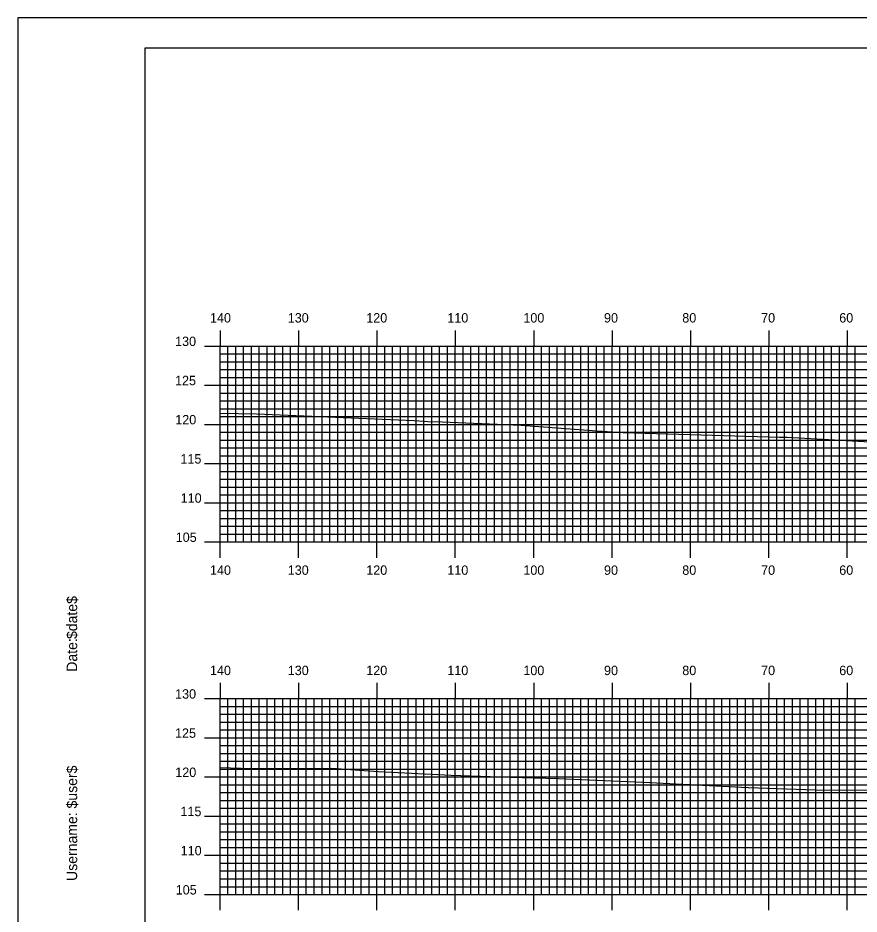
# Model space of a CAD drawing. Extents: x 1780680 to 1781023, y 442591 to 442811.
# Drawn here: x 1780679.6 to 1780786.9, y 442696.2 to 442810.5 of the extents above; entities that cross this region are included whole.
import ezdxf

# ---------------------------------------------------------------- set-up
doc = ezdxf.new("R2010")
doc.units = 0
for name, color, linetype in [('BORDER', 7, 'Continuous'), ('H_V ANNOTATION', 7, 'Continuous'), ('MAJOR', 7, 'Continuous'), ('MINOR', 7, 'Continuous'), ('PLOT BOUNDARY', 7, 'Continuous'), ('S_Roadway_Centerline', 7, 'Continuous')]:
    doc.layers.add(name, color=color, linetype=linetype)

msp = doc.modelspace()

# ---------------------------------------------------------------- linework, layer by layer
at = {"layer": 'BORDER'}
msp.add_lwpolyline([(1780695.78, 442596.67), (1781015.78, 442596.67), (1781015.78, 442806.67), (1780695.78, 442806.67)], close=True, dxfattribs=at)
at = {"layer": 'MAJOR'}
for p, q in [((1780705.38, 442770.67), (1780705.38, 442768.67)), ((1780715.38, 442770.67), (1780715.38, 442768.67)), ((1780725.38, 442770.67), (1780725.38, 442768.67)), ((1780735.38, 442770.67), (1780735.38, 442768.67)), ((1780745.38, 442770.67), (1780745.38, 442768.67)), ((1780755.38, 442770.67), (1780755.38, 442768.67)), ((1780765.38, 442770.67), (1780765.38, 442768.67)), ((1780775.38, 442770.67), (1780775.38, 442768.67)), ((1780785.38, 442770.67), (1780785.38, 442768.67)), ((1780703.38, 442768.67), (1780705.38, 442768.67)), ((1780705.38, 442768.67), (1780985.38, 442768.67)), ((1780705.38, 442743.67), (1780705.38, 442768.67)), ((1780705.38, 442743.67), (1780705.38, 442768.67)), ((1780705.38, 442768.67), (1780985.38, 442768.67)), ((1780715.38, 442743.67), (1780715.38, 442768.67)), ((1780725.38, 442743.67), (1780725.38, 442768.67)), ((1780735.38, 442743.67), (1780735.38, 442768.67)), ((1780745.38, 442743.67), (1780745.38, 442768.67)), ((1780755.38, 442743.67), (1780755.38, 442768.67)), ((1780765.38, 442743.67), (1780765.38, 442768.67)), ((1780775.38, 442743.67), (1780775.38, 442768.67)), ((1780785.38, 442743.67), (1780785.38, 442768.67)), ((1780703.38, 442763.67), (1780705.38, 442763.67)), ((1780705.38, 442763.67), (1780985.38, 442763.67)), ((1780703.38, 442758.67), (1780705.38, 442758.67)), ((1780705.38, 442758.67), (1780985.38, 442758.67)), ((1780703.38, 442753.67), (1780705.38, 442753.67)), ((1780705.38, 442753.67), (1780985.38, 442753.67)), ((1780703.38, 442748.67), (1780705.38, 442748.67)), ((1780705.38, 442748.67), (1780985.38, 442748.67)), ((1780703.38, 442743.67), (1780705.38, 442743.67)), ((1780705.38, 442743.67), (1780985.38, 442743.67)), ((1780705.38, 442743.67), (1780985.38, 442743.67)), ((1780705.38, 442741.66), (1780705.38, 442743.67)), ((1780715.38, 442741.66), (1780715.38, 442743.67)), ((1780725.38, 442741.66), (1780725.38, 442743.67)), ((1780735.38, 442741.66), (1780735.38, 442743.67)), ((1780745.38, 442741.66), (1780745.38, 442743.67)), ((1780755.38, 442741.66), (1780755.38, 442743.67)), ((1780765.38, 442741.66), (1780765.38, 442743.67)), ((1780775.38, 442741.66), (1780775.38, 442743.67)), ((1780785.38, 442741.66), (1780785.38, 442743.67)), ((1780705.38, 442725.67), (1780705.38, 442723.67)), ((1780715.38, 442725.67), (1780715.38, 442723.67)), ((1780725.38, 442725.67), (1780725.38, 442723.67)), ((1780735.38, 442725.67), (1780735.38, 442723.67)), ((1780745.38, 442725.67), (1780745.38, 442723.67)), ((1780755.38, 442725.67), (1780755.38, 442723.67)), ((1780765.38, 442725.67), (1780765.38, 442723.67)), ((1780775.38, 442725.67), (1780775.38, 442723.67)), ((1780785.38, 442725.67), (1780785.38, 442723.67)), ((1780703.38, 442723.67), (1780705.38, 442723.67)), ((1780705.38, 442723.67), (1780985.38, 442723.67)), ((1780705.38, 442698.67), (1780705.38, 442723.67)), ((1780705.38, 442698.67), (1780705.38, 442723.67)), ((1780705.38, 442723.67), (1780985.38, 442723.67)), ((1780715.38, 442698.67), (1780715.38, 442723.67)), ((1780725.38, 442698.67), (1780725.38, 442723.67)), ((1780735.38, 442698.67), (1780735.38, 442723.67)), ((1780745.38, 442698.67), (1780745.38, 442723.67)), ((1780755.38, 442698.67), (1780755.38, 442723.67)), ((1780765.38, 442698.67), (1780765.38, 442723.67)), ((1780775.38, 442698.67), (1780775.38, 442723.67)), ((1780785.38, 442698.67), (1780785.38, 442723.67)), ((1780703.38, 442718.67), (1780705.38, 442718.67)), ((1780705.38, 442718.67), (1780985.38, 442718.67)), ((1780703.38, 442713.67), (1780705.38, 442713.67)), ((1780705.38, 442713.67), (1780985.38, 442713.67)), ((1780703.38, 442708.67), (1780705.38, 442708.67)), ((1780705.38, 442708.67), (1780985.38, 442708.67)), ((1780703.38, 442703.67), (1780705.38, 442703.67)), ((1780705.38, 442703.67), (1780985.38, 442703.67)), ((1780703.38, 442698.67), (1780705.38, 442698.67)), ((1780705.38, 442698.67), (1780985.38, 442698.67)), ((1780705.38, 442698.67), (1780985.38, 442698.67)), ((1780705.38, 442696.66), (1780705.38, 442698.67)), ((1780715.38, 442696.66), (1780715.38, 442698.67)), ((1780725.38, 442696.66), (1780725.38, 442698.67)), ((1780735.38, 442696.66), (1780735.38, 442698.67)), ((1780745.38, 442696.66), (1780745.38, 442698.67)), ((1780755.38, 442696.66), (1780755.38, 442698.67)), ((1780765.38, 442696.66), (1780765.38, 442698.67)), ((1780775.38, 442696.66), (1780775.38, 442698.67)), ((1780785.38, 442696.66), (1780785.38, 442698.67))]:
    msp.add_line(p, q, dxfattribs=at)
at = {"layer": 'MINOR'}
for p, q in [((1780705.38, 442767.67), (1780985.38, 442767.67)), ((1780705.38, 442767.67), (1780707.39, 442767.67)), ((1780706.38, 442743.67), (1780706.38, 442768.67)), ((1780707.38, 442743.67), (1780707.38, 442768.67)), ((1780708.38, 442743.67), (1780708.38, 442768.67)), ((1780709.38, 442743.67), (1780709.38, 442768.67)), ((1780710.38, 442743.67), (1780710.38, 442768.67)), ((1780711.38, 442743.67), (1780711.38, 442768.67)), ((1780712.38, 442743.67), (1780712.38, 442768.67)), ((1780713.38, 442743.67), (1780713.38, 442768.67)), ((1780714.38, 442743.67), (1780714.38, 442768.67)), ((1780716.38, 442743.67), (1780716.38, 442768.67)), ((1780717.38, 442743.67), (1780717.38, 442768.67)), ((1780718.38, 442743.67), (1780718.38, 442768.67)), ((1780719.38, 442743.67), (1780719.38, 442768.67)), ((1780720.38, 442743.67), (1780720.38, 442768.67)), ((1780721.38, 442743.67), (1780721.38, 442768.67)), ((1780722.38, 442743.67), (1780722.38, 442768.67)), ((1780723.38, 442743.67), (1780723.38, 442768.67)), ((1780724.38, 442743.67), (1780724.38, 442768.67)), ((1780726.38, 442743.67), (1780726.38, 442768.67)), ((1780727.38, 442743.67), (1780727.38, 442768.67)), ((1780728.38, 442743.67), (1780728.38, 442768.67)), ((1780729.38, 442743.67), (1780729.38, 442768.67)), ((1780730.38, 442743.67), (1780730.38, 442768.67)), ((1780731.38, 442743.67), (1780731.38, 442768.67)), ((1780732.38, 442743.67), (1780732.38, 442768.67)), ((1780733.38, 442743.67), (1780733.38, 442768.67)), ((1780734.38, 442743.67), (1780734.38, 442768.67)), ((1780736.38, 442743.67), (1780736.38, 442768.67)), ((1780737.38, 442743.67), (1780737.38, 442768.67)), ((1780738.38, 442743.67), (1780738.38, 442768.67)), ((1780739.38, 442743.67), (1780739.38, 442768.67)), ((1780740.38, 442743.67), (1780740.38, 442768.67)), ((1780741.38, 442743.67), (1780741.38, 442768.67)), ((1780742.38, 442743.67), (1780742.38, 442768.67)), ((1780743.38, 442743.67), (1780743.38, 442768.67)), ((1780744.38, 442743.67), (1780744.38, 442768.67)), ((1780746.38, 442743.67), (1780746.38, 442768.67)), ((1780747.38, 442743.67), (1780747.38, 442768.67)), ((1780748.38, 442743.67), (1780748.38, 442768.67)), ((1780749.38, 442743.67), (1780749.38, 442768.67)), ((1780750.38, 442743.67), (1780750.38, 442768.67)), ((1780751.38, 442743.67), (1780751.38, 442768.67)), ((1780752.38, 442743.67), (1780752.38, 442768.67)), ((1780753.38, 442743.67), (1780753.38, 442768.67)), ((1780754.38, 442743.67), (1780754.38, 442768.67)), ((1780756.38, 442743.67), (1780756.38, 442768.67)), ((1780757.38, 442743.67), (1780757.38, 442768.67)), ((1780758.38, 442743.67), (1780758.38, 442768.67)), ((1780759.38, 442743.67), (1780759.38, 442768.67)), ((1780760.38, 442743.67), (1780760.38, 442768.67)), ((1780761.38, 442743.67), (1780761.38, 442768.67)), ((1780762.38, 442743.67), (1780762.38, 442768.67)), ((1780763.38, 442743.67), (1780763.38, 442768.67)), ((1780764.38, 442743.67), (1780764.38, 442768.67)), ((1780766.38, 442743.67), (1780766.38, 442768.67)), ((1780767.38, 442743.67), (1780767.38, 442768.67)), ((1780768.38, 442743.67), (1780768.38, 442768.67)), ((1780769.38, 442743.67), (1780769.38, 442768.67)), ((1780770.38, 442743.67), (1780770.38, 442768.67)), ((1780771.38, 442743.67), (1780771.38, 442768.67)), ((1780772.38, 442743.67), (1780772.38, 442768.67)), ((1780773.38, 442743.67), (1780773.38, 442768.67)), ((1780774.38, 442743.67), (1780774.38, 442768.67)), ((1780776.38, 442743.67), (1780776.38, 442768.67)), ((1780777.38, 442743.67), (1780777.38, 442768.67)), ((1780778.38, 442743.67), (1780778.38, 442768.67)), ((1780779.38, 442743.67), (1780779.38, 442768.67)), ((1780780.38, 442743.67), (1780780.38, 442768.67)), ((1780781.38, 442743.67), (1780781.38, 442768.67)), ((1780782.38, 442743.67), (1780782.38, 442768.67)), ((1780783.38, 442743.67), (1780783.38, 442768.67)), ((1780784.38, 442743.67), (1780784.38, 442768.67)), ((1780786.38, 442743.67), (1780786.38, 442768.67)), ((1780705.38, 442766.67), (1780985.38, 442766.67)), ((1780705.38, 442766.67), (1780707.39, 442766.67)), ((1780705.38, 442765.67), (1780985.38, 442765.67)), ((1780705.38, 442765.67), (1780707.39, 442765.67)), ((1780705.38, 442764.67), (1780985.38, 442764.67)), ((1780705.38, 442764.67), (1780707.39, 442764.67)), ((1780705.38, 442762.67), (1780985.38, 442762.67)), ((1780705.38, 442762.67), (1780707.39, 442762.67)), ((1780705.38, 442761.67), (1780985.38, 442761.67)), ((1780705.38, 442761.67), (1780707.39, 442761.67)), ((1780705.38, 442760.67), (1780985.38, 442760.67)), ((1780705.38, 442760.67), (1780707.39, 442760.67)), ((1780705.38, 442759.67), (1780985.38, 442759.67)), ((1780705.38, 442759.67), (1780707.39, 442759.67)), ((1780705.38, 442757.67), (1780985.38, 442757.67)), ((1780705.38, 442757.67), (1780707.39, 442757.67)), ((1780705.38, 442756.67), (1780985.38, 442756.67)), ((1780705.38, 442756.67), (1780707.39, 442756.67)), ((1780705.38, 442755.67), (1780985.38, 442755.67)), ((1780705.38, 442755.67), (1780707.39, 442755.67)), ((1780705.38, 442754.67), (1780985.38, 442754.67)), ((1780705.38, 442754.67), (1780707.39, 442754.67)), ((1780705.38, 442752.67), (1780985.38, 442752.67)), ((1780705.38, 442752.67), (1780707.39, 442752.67)), ((1780705.38, 442751.67), (1780985.38, 442751.67)), ((1780705.38, 442751.67), (1780707.39, 442751.67)), ((1780705.38, 442750.67), (1780985.38, 442750.67)), ((1780705.38, 442750.67), (1780707.39, 442750.67)), ((1780705.38, 442749.67), (1780985.38, 442749.67)), ((1780705.38, 442749.67), (1780707.39, 442749.67)), ((1780705.38, 442747.67), (1780985.38, 442747.67)), ((1780705.38, 442747.67), (1780707.39, 442747.67)), ((1780705.38, 442746.67), (1780985.38, 442746.67)), ((1780705.38, 442746.67), (1780707.39, 442746.67)), ((1780705.38, 442745.67), (1780985.38, 442745.67)), ((1780705.38, 442745.67), (1780707.39, 442745.67)), ((1780705.38, 442744.67), (1780985.38, 442744.67)), ((1780705.38, 442744.67), (1780707.39, 442744.67)), ((1780706.38, 442698.67), (1780706.38, 442723.67)), ((1780707.38, 442698.67), (1780707.38, 442723.67)), ((1780708.38, 442698.67), (1780708.38, 442723.67)), ((1780709.38, 442698.67), (1780709.38, 442723.67)), ((1780710.38, 442698.67), (1780710.38, 442723.67)), ((1780711.38, 442698.67), (1780711.38, 442723.67)), ((1780712.38, 442698.67), (1780712.38, 442723.67)), ((1780713.38, 442698.67), (1780713.38, 442723.67)), ((1780714.38, 442698.67), (1780714.38, 442723.67)), ((1780716.38, 442698.67), (1780716.38, 442723.67)), ((1780717.38, 442698.67), (1780717.38, 442723.67)), ((1780718.38, 442698.67), (1780718.38, 442723.67)), ((1780719.38, 442698.67), (1780719.38, 442723.67)), ((1780720.38, 442698.67), (1780720.38, 442723.67)), ((1780721.38, 442698.67), (1780721.38, 442723.67)), ((1780722.38, 442698.67), (1780722.38, 442723.67)), ((1780723.38, 442698.67), (1780723.38, 442723.67)), ((1780724.38, 442698.67), (1780724.38, 442723.67)), ((1780726.38, 442698.67), (1780726.38, 442723.67)), ((1780727.38, 442698.67), (1780727.38, 442723.67)), ((1780728.38, 442698.67), (1780728.38, 442723.67)), ((1780729.38, 442698.67), (1780729.38, 442723.67)), ((1780730.38, 442698.67), (1780730.38, 442723.67)), ((1780731.38, 442698.67), (1780731.38, 442723.67)), ((1780732.38, 442698.67), (1780732.38, 442723.67)), ((1780733.38, 442698.67), (1780733.38, 442723.67)), ((1780734.38, 442698.67), (1780734.38, 442723.67)), ((1780736.38, 442698.67), (1780736.38, 442723.67)), ((1780737.38, 442698.67), (1780737.38, 442723.67)), ((1780738.38, 442698.67), (1780738.38, 442723.67)), ((1780739.38, 442698.67), (1780739.38, 442723.67)), ((1780740.38, 442698.67), (1780740.38, 442723.67)), ((1780741.38, 442698.67), (1780741.38, 442723.67)), ((1780742.38, 442698.67), (1780742.38, 442723.67)), ((1780743.38, 442698.67), (1780743.38, 442723.67)), ((1780744.38, 442698.67), (1780744.38, 442723.67)), ((1780746.38, 442698.67), (1780746.38, 442723.67)), ((1780747.38, 442698.67), (1780747.38, 442723.67)), ((1780748.38, 442698.67), (1780748.38, 442723.67)), ((1780749.38, 442698.67), (1780749.38, 442723.67)), ((1780750.38, 442698.67), (1780750.38, 442723.67)), ((1780751.38, 442698.67), (1780751.38, 442723.67)), ((1780752.38, 442698.67), (1780752.38, 442723.67)), ((1780753.38, 442698.67), (1780753.38, 442723.67)), ((1780754.38, 442698.67), (1780754.38, 442723.67)), ((1780756.38, 442698.67), (1780756.38, 442723.67)), ((1780757.38, 442698.67), (1780757.38, 442723.67)), ((1780758.38, 442698.67), (1780758.38, 442723.67)), ((1780759.38, 442698.67), (1780759.38, 442723.67)), ((1780760.38, 442698.67), (1780760.38, 442723.67)), ((1780761.38, 442698.67), (1780761.38, 442723.67)), ((1780762.38, 442698.67), (1780762.38, 442723.67)), ((1780763.38, 442698.67), (1780763.38, 442723.67)), ((1780764.38, 442698.67), (1780764.38, 442723.67)), ((1780766.38, 442698.67), (1780766.38, 442723.67)), ((1780767.38, 442698.67), (1780767.38, 442723.67)), ((1780768.38, 442698.67), (1780768.38, 442723.67)), ((1780769.38, 442698.67), (1780769.38, 442723.67)), ((1780770.38, 442698.67), (1780770.38, 442723.67)), ((1780771.38, 442698.67), (1780771.38, 442723.67)), ((1780772.38, 442698.67), (1780772.38, 442723.67)), ((1780773.38, 442698.67), (1780773.38, 442723.67)), ((1780774.38, 442698.67), (1780774.38, 442723.67)), ((1780776.38, 442698.67), (1780776.38, 442723.67)), ((1780777.38, 442698.67), (1780777.38, 442723.67)), ((1780778.38, 442698.67), (1780778.38, 442723.67)), ((1780779.38, 442698.67), (1780779.38, 442723.67)), ((1780780.38, 442698.67), (1780780.38, 442723.67)), ((1780781.38, 442698.67), (1780781.38, 442723.67)), ((1780782.38, 442698.67), (1780782.38, 442723.67)), ((1780783.38, 442698.67), (1780783.38, 442723.67)), ((1780784.38, 442698.67), (1780784.38, 442723.67)), ((1780786.38, 442698.67), (1780786.38, 442723.67)), ((1780705.38, 442722.67), (1780985.38, 442722.67)), ((1780705.38, 442722.67), (1780707.39, 442722.67)), ((1780705.38, 442721.67), (1780985.38, 442721.67)), ((1780705.38, 442721.67), (1780707.39, 442721.67)), ((1780705.38, 442720.67), (1780985.38, 442720.67)), ((1780705.38, 442720.67), (1780707.39, 442720.67)), ((1780705.38, 442719.67), (1780985.38, 442719.67)), ((1780705.38, 442719.67), (1780707.39, 442719.67)), ((1780705.38, 442717.67), (1780985.38, 442717.67)), ((1780705.38, 442717.67), (1780707.39, 442717.67)), ((1780705.38, 442716.67), (1780985.38, 442716.67)), ((1780705.38, 442716.67), (1780707.39, 442716.67)), ((1780705.38, 442715.67), (1780985.38, 442715.67)), ((1780705.38, 442715.67), (1780707.39, 442715.67)), ((1780705.38, 442714.67), (1780985.38, 442714.67)), ((1780705.38, 442714.67), (1780707.39, 442714.67)), ((1780705.38, 442712.67), (1780985.38, 442712.67)), ((1780705.38, 442712.67), (1780707.39, 442712.67)), ((1780705.38, 442711.67), (1780985.38, 442711.67)), ((1780705.38, 442711.67), (1780707.39, 442711.67)), ((1780705.38, 442710.67), (1780985.38, 442710.67)), ((1780705.38, 442710.67), (1780707.39, 442710.67)), ((1780705.38, 442709.67), (1780985.38, 442709.67)), ((1780705.38, 442709.67), (1780707.39, 442709.67)), ((1780705.38, 442707.67), (1780985.38, 442707.67)), ((1780705.38, 442707.67), (1780707.39, 442707.67)), ((1780705.38, 442706.67), (1780985.38, 442706.67)), ((1780705.38, 442706.67), (1780707.39, 442706.67)), ((1780705.38, 442705.67), (1780985.38, 442705.67)), ((1780705.38, 442705.67), (1780707.39, 442705.67)), ((1780705.38, 442704.67), (1780985.38, 442704.67)), ((1780705.38, 442704.67), (1780707.39, 442704.67)), ((1780705.38, 442702.67), (1780985.38, 442702.67)), ((1780705.38, 442702.67), (1780707.39, 442702.67)), ((1780705.38, 442701.67), (1780985.38, 442701.67)), ((1780705.38, 442701.67), (1780707.39, 442701.67)), ((1780705.38, 442700.67), (1780985.38, 442700.67)), ((1780705.38, 442700.67), (1780707.39, 442700.67)), ((1780705.38, 442699.67), (1780985.38, 442699.67)), ((1780705.38, 442699.67), (1780707.39, 442699.67))]:
    msp.add_line(p, q, dxfattribs=at)
at = {"layer": 'PLOT BOUNDARY'}
msp.add_lwpolyline([(1780679.59, 442590.55), (1781019.59, 442590.55), (1781019.59, 442810.55), (1780679.59, 442810.55)], close=True, dxfattribs=at)
at = {"layer": 'S_Roadway_Centerline'}
for points in [[(1780705.38, 442760.11), (1780710.04, 442760.03), (1780730.12, 442759.15), (1780731.89, 442759.05), (1780733.72, 442758.98), (1780743.77, 442758.57), (1780753.43, 442757.83), (1780756.76, 442757.65), (1780776.72, 442757.06), (1780777.23, 442757.03), (1780777.71, 442757.02), (1780801.11, 442755.74)], [(1780705.38, 442714.9), (1780709.37, 442714.75), (1780719.64, 442714.8), (1780725.55, 442714.35), (1780734.86, 442713.92), (1780742.34, 442713.65), (1780748.53, 442713.46), (1780759.4, 442712.99), (1780772.8, 442712.31), (1780781.28, 442712.03), (1780788.27, 442711.98)]]:
    msp.add_lwpolyline(points, dxfattribs=at)

# ---------------------------------------------------------------- texts
at = {"layer": 'BORDER'}
for s, p in [('$date$', (1780687.15, 442731.28)), ('Date:', (1780687.15, 442727.1)), ('$user$', (1780687.15, 442709.65)), ('Username:', (1780687.15, 442700.4))]:
    msp.add_text(s, height=1.339, rotation=90, dxfattribs=at).set_placement(p)
at = {"layer": 'H_V ANNOTATION'}
for s, p in [('140', (1780704.09, 442771.67)), ('130', (1780714.01, 442771.67)), ('120', (1780724.02, 442771.67)), ('110', (1780734.36, 442771.67)), ('100', (1780744.06, 442771.67)), ('90', (1780754.35, 442771.67)), ('80', (1780764.33, 442771.67)), ('70', (1780774.39, 442771.67)), ('60', (1780784.35, 442771.67)), ('130', (1780699.64, 442768.67)), ('125', (1780699.63, 442763.67)), ('120', (1780699.66, 442758.67)), ('115', (1780700.32, 442753.67)), ('110', (1780700.35, 442748.67)), ('105', (1780699.72, 442743.67)), ('140', (1780704.09, 442739.47)), ('130', (1780714.01, 442739.47)), ('120', (1780724.02, 442739.47)), ('110', (1780734.36, 442739.47)), ('100', (1780744.06, 442739.47)), ('90', (1780754.35, 442739.47)), ('80', (1780764.33, 442739.47)), ('70', (1780774.39, 442739.47)), ('60', (1780784.35, 442739.47)), ('140', (1780704.09, 442726.67)), ('130', (1780714.01, 442726.67)), ('120', (1780724.02, 442726.67)), ('110', (1780734.36, 442726.67)), ('100', (1780744.06, 442726.67)), ('90', (1780754.35, 442726.67)), ('80', (1780764.33, 442726.67)), ('70', (1780774.39, 442726.67)), ('60', (1780784.35, 442726.67)), ('130', (1780699.64, 442723.67)), ('125', (1780699.63, 442718.67)), ('120', (1780699.66, 442713.67)), ('115', (1780700.32, 442708.67)), ('110', (1780700.35, 442703.67)), ('105', (1780699.72, 442698.67))]:
    msp.add_text(s, height=1.2, dxfattribs=at).set_placement(p)
at = {"layer": 'MAJOR'}
for p in [(1780705.37, 442743.67), (1780705.37, 442698.67)]:
    msp.add_text('-', height=0.012, dxfattribs=at).set_placement(p)

doc.saveas('drawing.dxf')
